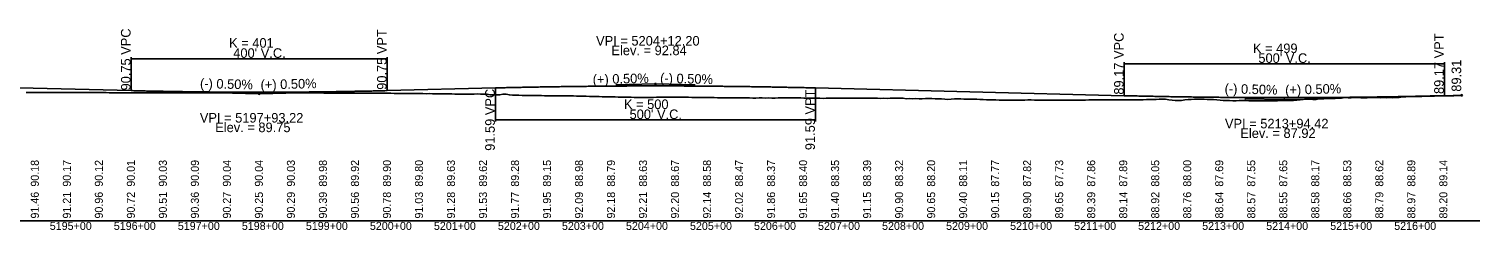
# Model space of a CAD drawing. Extents: x 2121671 to 2169879, y 557274 to 599957.
# Drawn here: x 2149002 to 2151268, y 592693 to 593008 of the extents above; entities that cross this region are included whole.
import ezdxf

# ---------------------------------------------------------------- set-up
doc = ezdxf.new("R2010")
doc.units = 0
for name, color, linetype in [('RD_DDB_GradeTX', 7, 'Continuous'), ('RD_DDB_Profile_EX', 7, 'Continuous'), ('RD_DDB_Profile_Lbl', 7, 'Continuous'), ('RD_DDB_Profile_PR', 7, 'Continuous'), ('RD_DDB_StaTX', 7, 'Continuous'), ('RD_DDB_StripGrade', 7, 'Continuous'), ('RD_DDB_VCLbl', 7, 'Continuous'), ('RD_GPK_Profile_Cell', 7, 'Continuous')]:
    doc.layers.add(name, color=color, linetype=linetype)

msp = doc.modelspace()

# ---------------------------------------------------------------- linework, layer by layer
at = {"layer": 'RD_DDB_GradeTX'}
for p, q in [((2149299.5, 592907.8), (2149360.5, 592906.2)), ((2149423.4, 592907.8), (2149362.5, 592906.2)), ((2149918.5, 592920.1), (2149979.4, 592921.6)), ((2150042.4, 592920.1), (2149981.4, 592921.6)), ((2150900.7, 592898.6), (2150961.7, 592897.1)), ((2151024.6, 592898.6), (2150963.7, 592897.1))]:
    msp.add_line(p, q, dxfattribs=at)
for centre in [(2149361.5, 592906.2), (2149980.4, 592921.7), (2151239.8, 592904), (2150962.7, 592897.1)]:
    msp.add_circle(centre, 1, dxfattribs=at)
at = {"layer": 'RD_DDB_Profile_EX'}
for points in [[(2148997.2, 592908.4), (2149002.2, 592908.4), (2149007.2, 592908.4), (2149012.2, 592908.4), (2149017.2, 592908.4), (2149022.2, 592908.3), (2149027.2, 592908.2), (2149032.2, 592908.2), (2149037.2, 592908.1), (2149042.2, 592908.1), (2149047.2, 592908.2), (2149052.2, 592908.2), (2149057.2, 592908.2), (2149062.2, 592908.3), (2149067.2, 592908.3), (2149072.2, 592908.3), (2149077.2, 592908.3), (2149082.2, 592908.2), (2149087.2, 592908.2), (2149092.2, 592908.2), (2149097.2, 592908.1), (2149102.2, 592908.1), (2149107.2, 592908.1), (2149112.2, 592908.1), (2149117.2, 592908.1), (2149122.2, 592908.1), (2149127.2, 592908), (2149132.2, 592908), (2149137.2, 592908), (2149142.2, 592907.9), (2149147.2, 592907.8), (2149152.2, 592907.7), (2149157.2, 592907.6), (2149162.2, 592907.5), (2149167.2, 592907.5), (2149172.2, 592907.5), (2149177.2, 592907.5), (2149182.2, 592907.6), (2149187.2, 592907.6), (2149192.2, 592907.6), (2149197.2, 592907.6), (2149202.2, 592907.6), (2149207.2, 592907.6), (2149212.2, 592907.6)], [(2149212.2, 592907.6), (2149217.2, 592907.6), (2149222.2, 592907.7), (2149227.2, 592907.7), (2149232.2, 592907.7), (2149237.2, 592907.7), (2149242.2, 592907.8), (2149247.2, 592907.8), (2149252.2, 592907.9), (2149257.2, 592907.9), (2149262.2, 592907.9), (2149267.2, 592907.9), (2149272.2, 592907.9), (2149277.2, 592907.8), (2149282.2, 592907.8), (2149287.2, 592907.8), (2149292.2, 592907.8), (2149297.2, 592907.7), (2149302.2, 592907.7), (2149307.2, 592907.7), (2149312.2, 592907.7), (2149317.2, 592907.7), (2149322.2, 592907.6), (2149327.2, 592907.6), (2149332.2, 592907.6), (2149337.2, 592907.6), (2149342.2, 592907.6), (2149347.2, 592907.6), (2149352.2, 592907.6), (2149357.2, 592907.7), (2149362.2, 592907.7), (2149367.2, 592907.7), (2149372.2, 592907.7), (2149377.2, 592907.7), (2149382.2, 592907.6), (2149387.2, 592907.6), (2149392.2, 592907.6), (2149397.2, 592907.6), (2149402.2, 592907.5), (2149407.2, 592907.5), (2149412.2, 592907.6), (2149417.2, 592907.6), (2149422.2, 592907.6), (2149427.2, 592907.7), (2149432.2, 592907.7), (2149437.2, 592907.7), (2149442.2, 592907.7), (2149447.2, 592907.6), (2149452.2, 592907.6), (2149457.2, 592907.5), (2149462.2, 592907.4), (2149467.2, 592907.4), (2149472.2, 592907.4), (2149477.2, 592907.4), (2149482.2, 592907.4), (2149487.2, 592907.4), (2149492.2, 592907.4), (2149497.2, 592907.3), (2149502.2, 592907.3), (2149507.2, 592907.2), (2149512.2, 592907.1), (2149517.2, 592907.1), (2149522.2, 592907), (2149527.2, 592907.1), (2149532.2, 592907.2), (2149537.2, 592907.2), (2149542.2, 592907.2), (2149547.2, 592907.2), (2149552.2, 592907.2), (2149557.2, 592907.1), (2149562.2, 592907.1), (2149567.2, 592907), (2149572.2, 592906.9), (2149577.2, 592906.8), (2149582.2, 592906.7), (2149587.2, 592906.7), (2149592.2, 592906.7), (2149597.2, 592906.6), (2149602.2, 592906.6), (2149607.2, 592906.6), (2149612.2, 592906.5), (2149617.2, 592906.5), (2149622.2, 592906.4), (2149627.2, 592906.5), (2149632.2, 592906.4), (2149637.2, 592906.3), (2149642.2, 592906.2), (2149647.2, 592906.1), (2149652.2, 592906.1), (2149657.2, 592906.1), (2149662.2, 592906.2), (2149667.2, 592905.7), (2149672.2, 592905.5), (2149677.2, 592905.5), (2149682.2, 592905.5), (2149687.2, 592905.5), (2149692.2, 592905.5), (2149697.2, 592905.6), (2149702.2, 592906), (2149707.2, 592905.9), (2149712.2, 592905.8)], [(2149712.2, 592905.8), (2149717.2, 592905.7), (2149722.2, 592904.7), (2149727.2, 592904.8), (2149732.2, 592904.7), (2149737.2, 592904.5), (2149742.2, 592905.5), (2149747.2, 592905.5), (2149752.2, 592904.6), (2149757.2, 592904.1), (2149762.2, 592904), (2149767.2, 592903.9), (2149772.2, 592903.8), (2149777.2, 592903.7), (2149782.2, 592903.7), (2149787.2, 592903.7), (2149792.2, 592903.6), (2149797.2, 592903.5), (2149802.2, 592903.4), (2149807.2, 592903.3), (2149812.2, 592903.2), (2149817.2, 592903.2), (2149822.2, 592903.2), (2149827.2, 592903.2), (2149832.2, 592903.3), (2149837.2, 592903.2), (2149842.2, 592903.3), (2149847.2, 592903.2), (2149852.2, 592902.8), (2149857.2, 592902.6), (2149862.2, 592902.3), (2149867.2, 592902.4), (2149872.2, 592902.3), (2149877.2, 592902.2), (2149882.2, 592902.1), (2149887.2, 592902.1), (2149892.2, 592901.8), (2149897.2, 592901.7), (2149902.2, 592901.7), (2149907.2, 592901.7), (2149912.2, 592901.7), (2149917.2, 592901.5), (2149922.2, 592901.1), (2149927.2, 592900.9), (2149932.2, 592900.8), (2149937.2, 592900.9), (2149942.2, 592901), (2149947.2, 592900.7), (2149952.2, 592900.4), (2149957.2, 592900.4), (2149962.2, 592900.6), (2149967.2, 592900.6), (2149972.2, 592900.6), (2149977.2, 592900.7), (2149982.2, 592900.9), (2149987.2, 592900.9), (2149992.2, 592900.8), (2149997.2, 592900.9), (2150002.2, 592901), (2150007.2, 592901.1), (2150012.2, 592900.9), (2150017.2, 592900.8), (2150022.2, 592900.8), (2150027.2, 592900.9), (2150032.2, 592900.8), (2150037.2, 592900.6), (2150042.2, 592900.5), (2150047.2, 592900.4), (2150052.2, 592900.4), (2150057.2, 592900.5), (2150062.2, 592900.5), (2150067.2, 592900.4), (2150072.2, 592900.2), (2150077.2, 592899.8), (2150082.2, 592899.7), (2150087.2, 592900), (2150092.2, 592900.1), (2150097.2, 592899.9), (2150102.2, 592899.9), (2150107.2, 592899.7), (2150112.2, 592899.8), (2150117.2, 592899.8), (2150122.2, 592899.9), (2150127.2, 592899.9), (2150132.2, 592899.6), (2150137.2, 592899.6), (2150142.2, 592899.8), (2150147.2, 592899.7), (2150152.2, 592899.4), (2150157.2, 592900), (2150162.2, 592899.4), (2150167.2, 592899.2), (2150172.2, 592899.8), (2150177.2, 592900), (2150182.2, 592899.7), (2150187.2, 592900), (2150192.2, 592900), (2150197.2, 592900), (2150202.2, 592900.1), (2150207.2, 592899.7), (2150212.2, 592899.4)], [(2151212.2, 592903.2), (2151217.2, 592903.2), (2151222.2, 592903), (2151227.2, 592903.1), (2151232.2, 592903.4), (2151237.2, 592903.7), (2151239.8, 592903.8)], [(2150212.2, 592899.4), (2150217.2, 592899.4), (2150222.2, 592899.5), (2150227.2, 592899.5), (2150232.2, 592899.4), (2150237.2, 592899.3), (2150242.2, 592899.1), (2150247.2, 592899.4), (2150252.2, 592899.5), (2150257.2, 592899.5), (2150262.2, 592899.4), (2150267.2, 592899.2), (2150272.2, 592899.4), (2150277.2, 592899.4), (2150282.2, 592899.4), (2150287.2, 592899.5), (2150292.2, 592899.6), (2150297.2, 592899.5), (2150302.2, 592899.4), (2150307.2, 592899.3), (2150312.2, 592899.4), (2150317.2, 592899.4), (2150322.2, 592899.3), (2150327.2, 592899.4), (2150332.2, 592899.1), (2150337.2, 592899.3), (2150342.2, 592898.9), (2150347.2, 592899.3), (2150352.2, 592899.2), (2150357.2, 592899.2), (2150362.2, 592899.2), (2150367.2, 592899.2), (2150372.2, 592898.6), (2150377.2, 592898.7), (2150382.2, 592898.6), (2150387.2, 592898.7), (2150392.2, 592898.6), (2150397.2, 592898.6), (2150402.2, 592898.7), (2150407.2, 592898.7), (2150412.2, 592898.7), (2150417.2, 592898.5), (2150422.2, 592898.5), (2150427.2, 592898.6), (2150432.2, 592897.8), (2150437.2, 592897.4), (2150442.2, 592898), (2150447.2, 592898.3), (2150452.2, 592898.3), (2150457.2, 592898.2), (2150462.2, 592898.1), (2150467.2, 592898.1), (2150472.2, 592897.6), (2150477.2, 592897.7), (2150482.2, 592897.6), (2150487.2, 592897.4), (2150492.2, 592897.1), (2150497.2, 592896.9), (2150502.2, 592896.7), (2150507.2, 592896.6), (2150512.2, 592896.6), (2150517.2, 592896.4), (2150522.2, 592896.1), (2150527.2, 592896.3), (2150532.2, 592896.3), (2150537.2, 592896.4), (2150542.2, 592896.3), (2150547.2, 592896.1), (2150552.2, 592896.3), (2150557.2, 592896.5), (2150562.2, 592896.7), (2150567.2, 592896.6), (2150572.2, 592896.5), (2150577.2, 592896.4), (2150582.2, 592896.3), (2150587.2, 592896.2), (2150592.2, 592896.1), (2150597.2, 592896.1), (2150602.2, 592896.1), (2150607.2, 592896.1), (2150612.2, 592896.1), (2150617.2, 592896.1), (2150622.2, 592896.1), (2150627.2, 592896.2), (2150632.2, 592896.2), (2150637.2, 592896.3), (2150642.2, 592896.3), (2150647.2, 592896.4), (2150652.2, 592896.5), (2150657.2, 592896.6), (2150662.2, 592896.7), (2150667.2, 592896.8), (2150672.2, 592896.9), (2150677.2, 592897), (2150682.2, 592896.9), (2150687.2, 592896.8), (2150692.2, 592896.8), (2150697.2, 592896.9), (2150702.2, 592896.9), (2150707.2, 592896.9), (2150712.2, 592896.9)], [(2150712.2, 592896.9), (2150717.2, 592896.9), (2150722.2, 592896.9), (2150727.2, 592897), (2150732.2, 592897), (2150737.2, 592897), (2150742.2, 592896.9), (2150747.2, 592897.2), (2150752.2, 592897.4), (2150757.2, 592897.4), (2150762.2, 592897.5), (2150767.2, 592897.7), (2150772.2, 592897.8), (2150777.2, 592897.7), (2150782.2, 592896.9), (2150787.2, 592896.3), (2150792.2, 592896), (2150797.2, 592895.8), (2150802.2, 592895.9), (2150807.2, 592896.6), (2150812.2, 592897.2), (2150817.2, 592897.5), (2150822.2, 592897.6), (2150827.2, 592897.6), (2150832.2, 592897.8), (2150837.2, 592897.6), (2150842.2, 592897.5), (2150847.2, 592897.5), (2150852.2, 592897.2), (2150857.2, 592896.8), (2150862.2, 592896.4), (2150867.2, 592896), (2150872.2, 592895.8), (2150877.2, 592895.7), (2150882.2, 592895.4), (2150887.2, 592895.2), (2150892.2, 592895.5), (2150897.2, 592895.9), (2150902.2, 592895.6), (2150907.2, 592895.3), (2150912.2, 592895.2), (2150917.2, 592895.2), (2150922.2, 592895.3), (2150927.2, 592895.3), (2150932.2, 592895.4), (2150937.2, 592895.4), (2150942.2, 592895.4), (2150947.2, 592895.4), (2150952.2, 592895.3), (2150957.2, 592895.5), (2150962.2, 592895.6), (2150967.2, 592895.7), (2150972.2, 592895.7), (2150977.2, 592896), (2150982.2, 592896.2), (2150987.2, 592896.8), (2150992.2, 592897.1), (2150997.2, 592897.9), (2151002.2, 592898), (2151007.2, 592897.3), (2151012.2, 592897.4), (2151017.2, 592898.2), (2151022.2, 592898.5), (2151027.2, 592898.9), (2151032.2, 592899), (2151037.2, 592899), (2151042.2, 592899), (2151047.2, 592899.2), (2151052.2, 592899.6), (2151057.2, 592900.2), (2151062.2, 592900.1), (2151067.2, 592900.1), (2151072.2, 592900.3), (2151077.2, 592900.2), (2151082.2, 592900), (2151087.2, 592900), (2151092.2, 592899.9), (2151097.2, 592900.2), (2151102.2, 592900.6), (2151107.2, 592900.7), (2151112.2, 592900.1), (2151117.2, 592900.7), (2151122.2, 592900.1), (2151127.2, 592900.2), (2151132.2, 592900.1), (2151137.2, 592900.4), (2151142.2, 592900.7), (2151147.2, 592901.3), (2151152.2, 592901.7), (2151157.2, 592901.8), (2151162.2, 592901.9), (2151167.2, 592901.9), (2151172.2, 592902), (2151177.2, 592902.2), (2151182.2, 592902.3), (2151187.2, 592902.4), (2151192.2, 592902.4), (2151197.2, 592902.6), (2151202.2, 592902.9), (2151207.2, 592903.2), (2151212.2, 592903.2)]]:
    msp.add_lwpolyline(points, dxfattribs=at)
at = {"layer": 'RD_DDB_Profile_PR'}
for p, q in [((2148964.7, 592916.1), (2149161.5, 592911.2)), ((2149561.5, 592911.2), (2149730.4, 592915.4)), ((2150230.4, 592915.4), (2150712.7, 592903.3)), ((2151212.7, 592903.3), (2151239.8, 592904))]:
    msp.add_line(p, q, dxfattribs=at)
for points in [[(2149161.5, 592911.2), (2149169.5, 592911), (2149177.5, 592910.8), (2149185.5, 592910.6), (2149193.5, 592910.5), (2149201.5, 592910.3), (2149209.5, 592910.2), (2149217.5, 592910), (2149225.5, 592909.9), (2149233.5, 592909.7), (2149241.5, 592909.6), (2149249.5, 592909.5), (2149257.5, 592909.4), (2149265.5, 592909.3), (2149273.5, 592909.2), (2149281.5, 592909.1), (2149289.5, 592909), (2149297.5, 592909), (2149305.5, 592908.9), (2149313.5, 592908.9), (2149321.5, 592908.8), (2149329.5, 592908.8), (2149337.5, 592908.8), (2149345.5, 592908.7), (2149353.5, 592908.7), (2149361.5, 592908.7), (2149369.5, 592908.7), (2149377.5, 592908.7), (2149385.5, 592908.8), (2149393.5, 592908.8), (2149401.5, 592908.8), (2149409.5, 592908.9), (2149417.5, 592908.9), (2149425.5, 592909), (2149433.5, 592909), (2149441.5, 592909.1), (2149449.5, 592909.2), (2149457.5, 592909.3), (2149465.5, 592909.4), (2149473.5, 592909.5), (2149481.5, 592909.6), (2149489.5, 592909.7), (2149497.5, 592909.9), (2149505.5, 592910), (2149513.5, 592910.2), (2149521.5, 592910.3), (2149529.5, 592910.5), (2149537.5, 592910.6), (2149545.5, 592910.8), (2149553.5, 592911), (2149561.5, 592911.2)], [(2149730.4, 592915.4), (2149740.4, 592915.7), (2149750.4, 592915.9), (2149760.4, 592916.1), (2149770.4, 592916.3), (2149780.4, 592916.6), (2149790.4, 592916.7), (2149800.4, 592916.9), (2149810.4, 592917.1), (2149820.4, 592917.3), (2149830.4, 592917.4), (2149840.4, 592917.6), (2149850.4, 592917.7), (2149860.4, 592917.8), (2149870.4, 592917.9), (2149880.4, 592918), (2149890.4, 592918.1), (2149900.4, 592918.2), (2149910.4, 592918.3), (2149920.4, 592918.4), (2149930.4, 592918.4), (2149940.4, 592918.5), (2149950.4, 592918.5), (2149960.4, 592918.5), (2149970.4, 592918.5), (2149980.4, 592918.5), (2149990.4, 592918.5), (2150000.4, 592918.5), (2150010.4, 592918.5), (2150020.4, 592918.5), (2150030.4, 592918.4), (2150040.4, 592918.4), (2150050.4, 592918.3), (2150060.4, 592918.2), (2150070.4, 592918.1), (2150080.4, 592918), (2150090.4, 592917.9), (2150100.4, 592917.8), (2150110.4, 592917.7), (2150120.4, 592917.6), (2150130.4, 592917.4), (2150140.4, 592917.3), (2150150.4, 592917.1), (2150160.4, 592916.9), (2150170.4, 592916.7), (2150180.4, 592916.5), (2150190.4, 592916.3), (2150200.4, 592916.1), (2150210.4, 592915.9), (2150220.4, 592915.7), (2150230.4, 592915.4)], [(2150712.7, 592903.3), (2150722.7, 592903.1), (2150732.7, 592902.8), (2150742.7, 592902.6), (2150752.7, 592902.4), (2150762.7, 592902.2), (2150772.7, 592902), (2150782.7, 592901.8), (2150792.7, 592901.6), (2150802.7, 592901.5), (2150812.7, 592901.3), (2150822.7, 592901.2), (2150832.7, 592901), (2150842.7, 592900.9), (2150852.7, 592900.8), (2150862.7, 592900.7), (2150872.7, 592900.6), (2150882.7, 592900.5), (2150892.7, 592900.4), (2150902.7, 592900.4), (2150912.7, 592900.3), (2150922.7, 592900.3), (2150932.7, 592900.2), (2150942.7, 592900.2), (2150952.7, 592900.2), (2150962.7, 592900.2), (2150972.7, 592900.2), (2150982.7, 592900.2), (2150992.7, 592900.2), (2151002.7, 592900.3), (2151012.7, 592900.3), (2151022.7, 592900.4), (2151032.7, 592900.4), (2151042.7, 592900.5), (2151052.7, 592900.6), (2151062.7, 592900.7), (2151072.7, 592900.8), (2151082.7, 592900.9), (2151092.7, 592901.1), (2151102.7, 592901.2), (2151112.7, 592901.3), (2151122.7, 592901.5), (2151132.7, 592901.7), (2151142.7, 592901.8), (2151152.7, 592902), (2151162.7, 592902.2), (2151172.7, 592902.4), (2151182.7, 592902.6), (2151192.7, 592902.9), (2151202.7, 592903.1), (2151212.7, 592903.3)]]:
    msp.add_spline(points, degree=3, dxfattribs=at)
at = {"layer": 'RD_DDB_VCLbl'}
for p, q in [((2149161.5, 592963.7), (2149161.5, 592911.2)), ((2149161.5, 592961.2), (2149561.5, 592961.2)), ((2149561.5, 592963.7), (2149561.5, 592911.2)), ((2150712.7, 592955.8), (2150712.7, 592903.3)), ((2150712.7, 592953.3), (2151212.7, 592953.3)), ((2151212.7, 592955.8), (2151212.7, 592903.3)), ((2149730.4, 592862.9), (2149730.4, 592915.4)), ((2150230.4, 592862.9), (2150230.4, 592915.4)), ((2149730.4, 592865.4), (2150230.4, 592865.4))]:
    msp.add_line(p, q, dxfattribs=at)
at = {"layer": 'RD_GPK_Profile_Cell'}
msp.add_line((2146668.2, 592707.5), (2151268.2, 592707.5), dxfattribs=at)
msp.add_line((2146668.2, 592707.5), (2151268.2, 592707.5), dxfattribs=at)

# ---------------------------------------------------------------- texts
at = {"layer": 'RD_DDB_GradeTX'}
for s, rotation, p in [('(-) 0.50%', 358.5698, (2149268.8, 592915.2)), ('(+) 0.50%', 1.4298, (2149363.7, 592912.9)), ('(+) 0.50%', 1.4298, (2149882.5, 592921.2)), ('(-) 0.50%', 358.5653, (2149987.5, 592923.5)), ('(-) 0.50%', 358.5653, (2150869.2, 592907)), ('(+) 0.50%', 1.4367, (2150964.1, 592904.8))]:
    msp.add_text(s, height=15, rotation=rotation, dxfattribs=at).set_placement(p)
at = {"layer": 'RD_DDB_Profile_Lbl'}
for s, p in [('VPI = 5204+12.20', (2149887.6, 592981.7)), ('Elev. = 92.84', (2149911.6, 592966.7)), ('VPI = 5197+93.22', (2149268.7, 592861.2)), ('Elev. = 89.75', (2149292.7, 592846.2)), ('VPI = 5213+94.42', (2150869.9, 592852.1)), ('Elev. = 87.92', (2150893.9, 592837.1))]:
    msp.add_text(s, height=15, dxfattribs=at).set_placement(p)
msp.add_text('89.31', height=15, rotation=90, dxfattribs=at).set_placement((2151238.9, 592909.5))
at = {"layer": 'RD_DDB_StaTX'}
for s, p in [('5195+00', (2149034.3, 592693.2)), ('5196+00', (2149134.3, 592693.2)), ('5197+00', (2149234.3, 592693.2)), ('5198+00', (2149334.3, 592693.2)), ('5199+00', (2149434.3, 592693.2)), ('5200+00', (2149534.3, 592693.2)), ('5201+00', (2149634.3, 592693.2)), ('5202+00', (2149734.3, 592693.2)), ('5203+00', (2149834.3, 592693.2)), ('5204+00', (2149934.3, 592693.2)), ('5205+00', (2150034.3, 592693.2)), ('5206+00', (2150134.3, 592693.2)), ('5207+00', (2150234.3, 592693.2)), ('5208+00', (2150334.3, 592693.2)), ('5209+00', (2150434.3, 592693.2)), ('5210+00', (2150534.3, 592693.2)), ('5211+00', (2150634.3, 592693.2)), ('5212+00', (2150734.3, 592693.2)), ('5213+00', (2150834.3, 592693.2)), ('5214+00', (2150934.3, 592693.2)), ('5215+00', (2151034.3, 592693.2)), ('5216+00', (2151134.3, 592693.2))]:
    msp.add_text(s, height=12.5, dxfattribs=at).set_placement(p)
at = {"layer": 'RD_DDB_StripGrade'}
for s, height, p in [('90.75 VPC', 15, (2149160.5, 592911.5)), ('90.75 VPT', 15, (2149560.5, 592912.5)), ('89.17 VPC', 15, (2150711.7, 592904.9)), ('89.17 VPT', 15, (2151211.7, 592905.9)), ('91.59 VPC', 15, (2149729.4, 592817)), ('91.59 VPT', 15, (2150229.4, 592818)), ('90.18', 12.5, (2149017.2, 592760.9)), ('90.17', 12.5, (2149067.2, 592760.9)), ('90.12', 12.5, (2149117.2, 592760.9)), ('90.01', 12.5, (2149167.2, 592760.9)), ('90.03', 12.5, (2149217.2, 592760.9)), ('90.09', 12.5, (2149267.2, 592760.9)), ('90.04', 12.5, (2149317.2, 592760.9)), ('90.04', 12.5, (2149367.2, 592760.9)), ('90.03', 12.5, (2149417.2, 592760.9)), ('89.98', 12.5, (2149467.2, 592760.9)), ('89.92', 12.5, (2149517.2, 592760.9)), ('89.90', 12.5, (2149567.2, 592760.9)), ('89.80', 12.5, (2149617.2, 592760.9)), ('89.63', 12.5, (2149667.2, 592760.9)), ('89.62', 12.5, (2149717.2, 592760.9)), ('89.28', 12.5, (2149767.2, 592760.9)), ('89.15', 12.5, (2149817.2, 592760.9)), ('88.98', 12.5, (2149867.2, 592760.9)), ('88.79', 12.5, (2149917.2, 592760.9)), ('88.63', 12.5, (2149967.2, 592760.9)), ('88.67', 12.5, (2150017.2, 592760.9)), ('88.58', 12.5, (2150067.2, 592760.9)), ('88.47', 12.5, (2150117.2, 592760.9)), ('88.37', 12.5, (2150167.2, 592760.9)), ('88.40', 12.5, (2150217.2, 592760.9)), ('88.35', 12.5, (2150267.2, 592760.9)), ('88.39', 12.5, (2150317.2, 592760.9)), ('88.32', 12.5, (2150367.2, 592760.9)), ('88.20', 12.5, (2150417.2, 592760.9)), ('88.11', 12.5, (2150467.2, 592760.9)), ('87.77', 12.5, (2150517.2, 592760.9)), ('87.82', 12.5, (2150567.2, 592760.9)), ('87.73', 12.5, (2150617.2, 592760.9)), ('87.86', 12.5, (2150667.2, 592760.9)), ('87.89', 12.5, (2150717.2, 592760.9)), ('88.05', 12.5, (2150767.2, 592760.9)), ('88.00', 12.5, (2150817.2, 592760.9)), ('87.69', 12.5, (2150867.2, 592760.9)), ('87.55', 12.5, (2150917.2, 592760.9)), ('87.65', 12.5, (2150967.2, 592760.9)), ('88.17', 12.5, (2151017.2, 592760.9)), ('88.53', 12.5, (2151067.2, 592760.9)), ('88.62', 12.5, (2151117.2, 592760.9)), ('88.89', 12.5, (2151167.2, 592760.9)), ('89.14', 12.5, (2151217.2, 592760.9)), ('91.46', 12.5, (2149017.2, 592711)), ('91.21', 12.5, (2149067.2, 592711)), ('90.96', 12.5, (2149117.2, 592711)), ('90.72', 12.5, (2149167.2, 592711)), ('90.51', 12.5, (2149217.2, 592711)), ('90.36', 12.5, (2149267.2, 592711)), ('90.27', 12.5, (2149317.2, 592711)), ('90.25', 12.5, (2149367.2, 592711)), ('90.29', 12.5, (2149417.2, 592711)), ('90.39', 12.5, (2149467.2, 592711)), ('90.56', 12.5, (2149517.2, 592711)), ('90.78', 12.5, (2149567.2, 592711)), ('91.03', 12.5, (2149617.2, 592711)), ('91.28', 12.5, (2149667.2, 592711)), ('91.53', 12.5, (2149717.2, 592711)), ('91.77', 12.5, (2149767.2, 592711)), ('91.95', 12.5, (2149817.2, 592711)), ('92.09', 12.5, (2149867.2, 592711)), ('92.18', 12.5, (2149917.2, 592711)), ('92.21', 12.5, (2149967.2, 592711)), ('92.20', 12.5, (2150017.2, 592711)), ('92.14', 12.5, (2150067.2, 592711)), ('92.02', 12.5, (2150117.2, 592711)), ('91.86', 12.5, (2150167.2, 592711)), ('91.65', 12.5, (2150217.2, 592711)), ('91.40', 12.5, (2150267.2, 592711)), ('91.15', 12.5, (2150317.2, 592711)), ('90.90', 12.5, (2150367.2, 592711)), ('90.65', 12.5, (2150417.2, 592711)), ('90.40', 12.5, (2150467.2, 592711)), ('90.15', 12.5, (2150517.2, 592711)), ('89.90', 12.5, (2150567.2, 592711)), ('89.65', 12.5, (2150617.2, 592711)), ('89.39', 12.5, (2150667.2, 592711)), ('89.14', 12.5, (2150717.2, 592711)), ('88.92', 12.5, (2150767.2, 592711)), ('88.76', 12.5, (2150817.2, 592711)), ('88.64', 12.5, (2150867.2, 592711)), ('88.57', 12.5, (2150917.2, 592711)), ('88.55', 12.5, (2150967.2, 592711)), ('88.58', 12.5, (2151017.2, 592711)), ('88.66', 12.5, (2151067.2, 592711)), ('88.79', 12.5, (2151117.2, 592711)), ('88.97', 12.5, (2151167.2, 592711)), ('89.20', 12.5, (2151217.2, 592711))]:
    msp.add_text(s, height=height, rotation=90, dxfattribs=at).set_placement(p)
at = {"layer": 'RD_DDB_VCLbl'}
for s, p in [('K = 401', (2149314.4, 592978.4)), ("400' V.C.", (2149320.9, 592962.5)), ('K = 499', (2150913.6, 592969.9)), ("500' V.C.", (2150922.1, 592954.6)), ('K = 500', (2149931.1, 592882.4)), ("500' V.C.", (2149939.9, 592866.7))]:
    msp.add_text(s, height=15, dxfattribs=at).set_placement(p)

doc.saveas('drawing.dxf')
